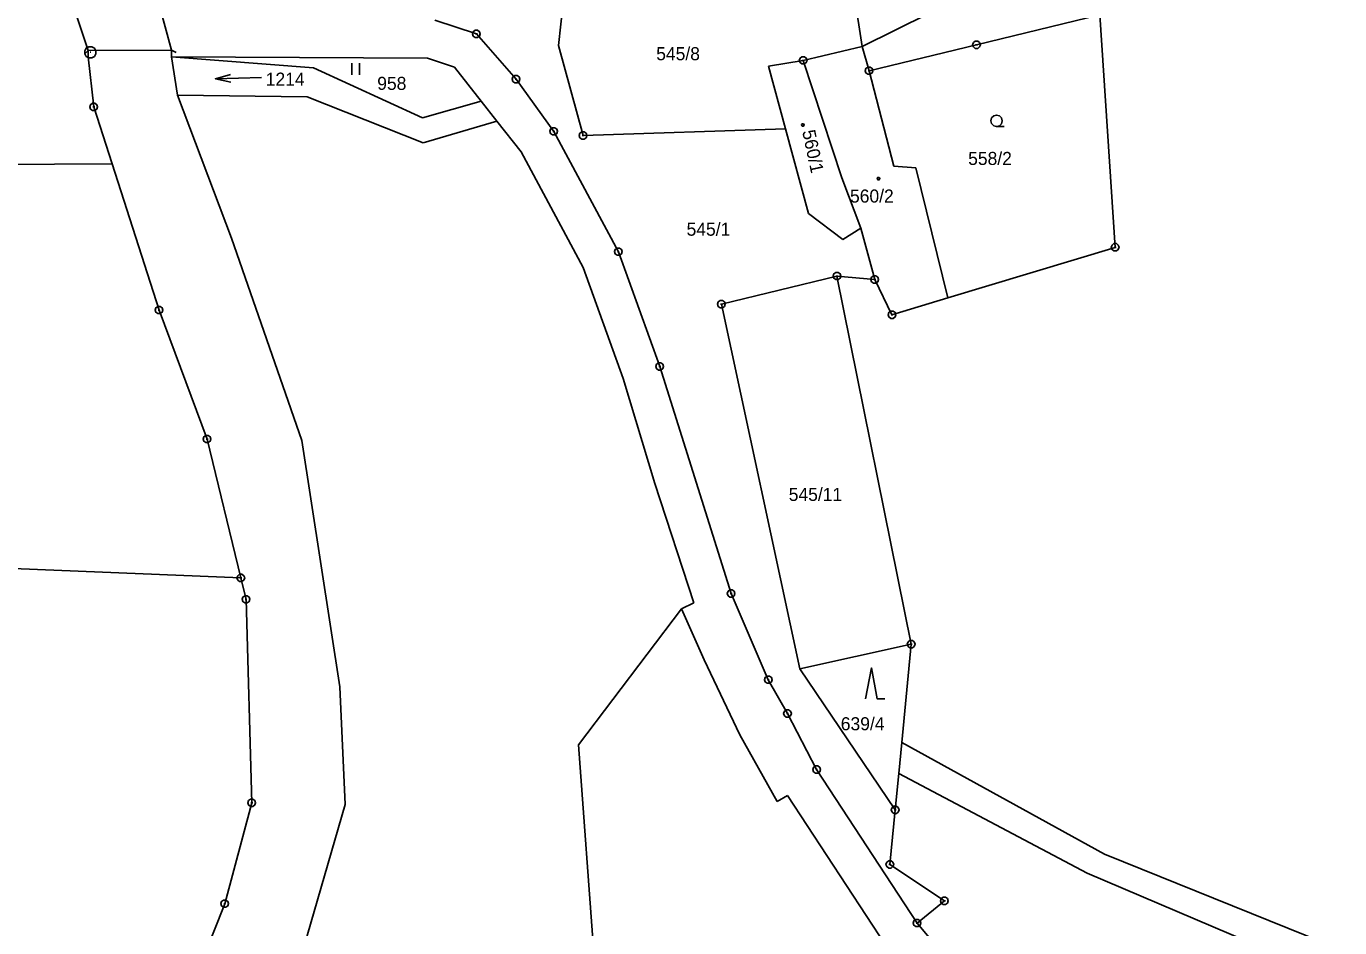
# Model space of a CAD drawing. Extents: x -812394 to -807601, y -1013098 to -1009266.
# Drawn here: x -809003.5 to -808832.6, y -1011807.7 to -1011690.5 of the extents above; entities that cross this region are included whole.
import ezdxf

# ---------------------------------------------------------------- set-up
doc = ezdxf.new("R2010")
doc.units = 0
for name, color, linetype in [('KN_HRANICE', 7, 'Continuous'), ('KN_KULTURY', 7, 'Continuous'), ('KN_MEZNIKY', 7, 'Continuous'), ('KN_PARCELY', 7, 'Continuous'), ('KN_SLUCKY', 7, 'Continuous')]:
    doc.layers.add(name, color=color, linetype=linetype)

# ---------------------------------------------------------------- blocks, each defined once
blk = doc.blocks.new('101')
blk.add_line((-0.05, 0), (0.05, 0))
blk.add_lwpolyline([(0.19, 0.72), (0.53, 0.53), (0.72, 0.19), (0.72, -0.2), (0.53, -0.54), (0.19, -0.73), (-0.2, -0.73), (-0.54, -0.54), (-0.73, -0.2), (-0.73, 0.19), (-0.54, 0.53), (-0.2, 0.72), (0.19, 0.72)])
blk = doc.blocks.new('304')
blk.add_lwpolyline([(0, 0), (-0.38, 0.1), (-0.65, 0.37), (-0.75, 0.74), (-0.65, 1.11), (-0.38, 1.38), (-0.01, 1.48), (0.36, 1.38), (0.63, 1.11), (0.73, 0.73), (0.63, 0.35), (0.36, 0.08), (-0.02, -0.02), (0.98, -0.02)])
blk = doc.blocks.new('306')
for p, q in [((-0.5, 1.5), (-0.5, 0)), ((0.5, 0), (0.5, 1.5))]:
    blk.add_line(p, q)
blk = doc.blocks.new('308')
blk.add_lwpolyline([(-0.75, 0), (0, 4), (0.75, 0), (1.75, 0)])
blk = doc.blocks.new('NAHRADNI_SYMBOL')
blk.add_lwpolyline([(0.09, 0.15), (0.18, 0), (0.09, -0.15), (-0.09, -0.15), (-0.18, 0), (-0.09, 0.15), (0.09, 0.15)])
blk = doc.blocks.new('802')
blk.add_line((-3, 0), (3, 0))
blk.add_lwpolyline([(1, 0.5), (3, 0), (1, -0.5)])
blk = doc.blocks.new('105')
blk.add_line((-0.12, 0), (0.12, 0))
blk.add_lwpolyline([(0.15, 0.48), (0.4, 0.3), (0.5, 0.01), (0.4, -0.28), (0.15, -0.46), (-0.16, -0.46), (-0.41, -0.28), (-0.51, 0.01), (-0.41, 0.3), (-0.16, 0.48), (0.15, 0.48)])
blk = doc.blocks.new('4201')
blk.add_line((0, 0), (-0.5, -0.5))

msp = doc.modelspace()

# ---------------------------------------------------------------- linework, layer by layer
at = {"layer": 'KN_HRANICE'}
for p, q in [((-808896.85, -1011679.68), (-808894.75, -1011693.18)), ((-808894.75, -1011693.18), (-808871.71, -1011681.7)), ((-808995.44, -1011693.68), (-808997.44, -1011687.71)), ((-808984.63, -1011693.65), (-808986.26, -1011687.57)), ((-808933.67, -1011687.5), (-808934.28, -1011693.03)), ((-808879.89, -1011692.95), (-808863.84, -1011689.06)), ((-808861.85, -1011719.28), (-808863.84, -1011689.06)), ((-808950.35, -1011689.74), (-808944.94, -1011691.54)), ((-808944.94, -1011691.54), (-808939.79, -1011697.43)), ((-808995.44, -1011694.53), (-808995.44, -1011693.68)), ((-808984.63, -1011694.5), (-808984.63, -1011693.65)), ((-808934.28, -1011693.03), (-808931.07, -1011704.75)), ((-808902.44, -1011694.98), (-808894.75, -1011693.18)), ((-808894.75, -1011693.18), (-808893.86, -1011696.32)), ((-808893.86, -1011696.32), (-808879.89, -1011692.95)), ((-808994.72, -1011701.03), (-808995.44, -1011694.53)), ((-808984.63, -1011694.5), (-808951.31, -1011694.69)), ((-808966.16, -1011695.95), (-808984.63, -1011694.5)), ((-808983.84, -1011699.49), (-808984.63, -1011694.5)), ((-808951.96, -1011702.46), (-808966.16, -1011695.95)), ((-808951.31, -1011694.69), (-808947.81, -1011695.86)), ((-808947.81, -1011695.86), (-808944.33, -1011700.27)), ((-808902.44, -1011694.98), (-808906.94, -1011695.74)), ((-808904.75, -1011703.86), (-808906.94, -1011695.74)), ((-808897.41, -1011710.26), (-808902.44, -1011694.98)), ((-808939.79, -1011697.43), (-808934.88, -1011704.2)), ((-808893.86, -1011696.32), (-808890.65, -1011708.71)), ((-808994.72, -1011701.03), (-808992.34, -1011708.44)), ((-808944.33, -1011700.27), (-808951.96, -1011702.46)), ((-808944.33, -1011700.27), (-808942.28, -1011702.87)), ((-808951.87, -1011705.7), (-808942.28, -1011702.87)), ((-808942.28, -1011702.87), (-808939.13, -1011706.86)), ((-808934.88, -1011704.2), (-808926.48, -1011719.85)), ((-808931.07, -1011704.75), (-808904.75, -1011703.86)), ((-808904.75, -1011703.86), (-808901.77, -1011714.86)), ((-808939.13, -1011706.86), (-808931.06, -1011721.89)), ((-809019.35, -1011708.55), (-808992.34, -1011708.44)), ((-808992.34, -1011708.44), (-808986.23, -1011727.44)), ((-808890.65, -1011708.71), (-808887.77, -1011708.95)), ((-808887.77, -1011708.95), (-808883.64, -1011725.86)), ((-808894.93, -1011716.8), (-808897.41, -1011710.26)), ((-808901.77, -1011714.86), (-808897.28, -1011718.24)), ((-808897.28, -1011718.24), (-808894.93, -1011716.8)), ((-808893.13, -1011723.47), (-808894.93, -1011716.8)), ((-808926.48, -1011719.85), (-808921.09, -1011734.77)), ((-808861.85, -1011719.28), (-808883.64, -1011725.86)), ((-808931.06, -1011721.89), (-808925.84, -1011736.34)), ((-808913.07, -1011726.68), (-808898.05, -1011723.01)), ((-808888.39, -1011770.88), (-808898.05, -1011723.01)), ((-808898.05, -1011723.01), (-808893.13, -1011723.47)), ((-808893.13, -1011723.47), (-808890.89, -1011728.05)), ((-808902.86, -1011774.06), (-808913.07, -1011726.68)), ((-808883.64, -1011725.86), (-808890.89, -1011728.05)), ((-808979.98, -1011744.21), (-808986.23, -1011727.44)), ((-808921.09, -1011734.77), (-808911.81, -1011764.29)), ((-808925.84, -1011736.34), (-808921.75, -1011749.99)), ((-808975.59, -1011762.27), (-808979.98, -1011744.21)), ((-808921.75, -1011749.99), (-808916.67, -1011765.52)), ((-809026.09, -1011760.16), (-808975.59, -1011762.27)), ((-808974.91, -1011765.05), (-808975.59, -1011762.27)), ((-808911.81, -1011764.29), (-808906.98, -1011775.5)), ((-808974.17, -1011791.5), (-808974.91, -1011765.05)), ((-808916.67, -1011765.52), (-808918.26, -1011766.3)), ((-808918.26, -1011766.3), (-808931.65, -1011783.96)), ((-808918.26, -1011766.3), (-808915.32, -1011772.9)), ((-808902.86, -1011774.06), (-808888.39, -1011770.88)), ((-808889.62, -1011783.66), (-808888.39, -1011770.88)), ((-808915.32, -1011772.9), (-808910.67, -1011782.65)), ((-808890.47, -1011792.42), (-808902.86, -1011774.06)), ((-808906.98, -1011775.5), (-808904.48, -1011779.89)), ((-808904.48, -1011779.89), (-808900.69, -1011787.19)), ((-808910.67, -1011782.65), (-808905.83, -1011791.31)), ((-808931.65, -1011783.96), (-808923.83, -1011891.74)), ((-808890.01, -1011787.67), (-808889.62, -1011783.66)), ((-808889.62, -1011783.66), (-808863.23, -1011798.16)), ((-808900.69, -1011787.19), (-808887.62, -1011807.14)), ((-808890.47, -1011792.42), (-808890.01, -1011787.67)), ((-808865.49, -1011800.66), (-808890.01, -1011787.67)), ((-808977.69, -1011804.62), (-808974.17, -1011791.5)), ((-808905.83, -1011791.31), (-808904.46, -1011790.57)), ((-808904.46, -1011790.57), (-808891.7, -1011810.04)), ((-808891.16, -1011799.52), (-808890.47, -1011792.42)), ((-808863.23, -1011798.16), (-808822.56, -1011814.57)), ((-808884.06, -1011804.26), (-808891.16, -1011799.52)), ((-808824.78, -1011817.93), (-808865.49, -1011800.66)), ((-808986.12, -1011825.88), (-808977.69, -1011804.62)), ((-808887.62, -1011807.14), (-808884.06, -1011804.26)), ((-808878.74, -1011817.7), (-808887.62, -1011807.14))]:
    msp.add_line(p, q, dxfattribs=at)
for points in [[(-808951.87, -1011705.7), (-808966.96, -1011699.71), (-808983.84, -1011699.49)], [(-808959.35, -1011971.59), (-808962.28, -1011929.28), (-808966.55, -1011904.05), (-808970.77, -1011886.31), (-808975.49, -1011831.97), (-808967.41, -1011810.26), (-808962, -1011791.72), (-808962.72, -1011776.44), (-808967.65, -1011744.41), (-808976.79, -1011718.1), (-808983.84, -1011699.49)]]:
    msp.add_lwpolyline(points, dxfattribs=at)
at = {"layer": 'KN_SLUCKY'}
msp.add_line((-808995.44, -1011693.68), (-808984.63, -1011693.65), dxfattribs=at)

# ---------------------------------------------------------------- block references
at = {"layer": 'KN_KULTURY'}
for name, p in [('306', (-808960.66, -1011696.83)), ('304', (-808877.28, -1011703.56)), ('NAHRADNI_SYMBOL', (-808902.48, -1011703.36)), ('NAHRADNI_SYMBOL', (-808892.64, -1011710.33)), ('308', (-808893.57, -1011777.97))]:
    msp.add_blockref(name, p, dxfattribs=at)
at = {"layer": 'KN_KULTURY', "rotation": -178.25778700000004}
msp.add_blockref('802', (-808975.9, -1011697.27), dxfattribs=at)
at = {"layer": 'KN_MEZNIKY'}
for name, p in [('105', (-808944.94, -1011691.54)), ('105', (-808879.89, -1011692.95)), ('101', (-808995.16, -1011693.91)), ('105', (-808902.44, -1011694.98)), ('105', (-808893.86, -1011696.32)), ('105', (-808939.79, -1011697.43)), ('105', (-808994.72, -1011701.03)), ('105', (-808934.88, -1011704.2)), ('105', (-808931.07, -1011704.75)), ('105', (-808926.48, -1011719.85)), ('105', (-808861.85, -1011719.28)), ('105', (-808898.05, -1011723.01)), ('105', (-808893.13, -1011723.47)), ('105', (-808913.07, -1011726.68)), ('105', (-808986.23, -1011727.44)), ('105', (-808890.89, -1011728.05)), ('105', (-808921.09, -1011734.77)), ('105', (-808979.98, -1011744.21)), ('105', (-808975.59, -1011762.27)), ('105', (-808911.81, -1011764.29)), ('105', (-808974.91, -1011765.05)), ('105', (-808888.39, -1011770.88)), ('105', (-808906.98, -1011775.5)), ('105', (-808904.48, -1011779.89)), ('105', (-808900.69, -1011787.19)), ('105', (-808974.17, -1011791.5)), ('105', (-808890.47, -1011792.42)), ('105', (-808891.16, -1011799.52)), ('105', (-808977.69, -1011804.62)), ('105', (-808884.06, -1011804.26)), ('105', (-808887.62, -1011807.14))]:
    msp.add_blockref(name, p, dxfattribs=at)
at = {"layer": 'KN_SLUCKY'}
msp.add_blockref('4201', (-808995.44, -1011693.68), dxfattribs=at)
at = {"layer": 'KN_SLUCKY', "rotation": 108.91927700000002}
msp.add_blockref('4201', (-808984.63, -1011693.65), dxfattribs=at)

# ---------------------------------------------------------------- texts
at = {"layer": 'KN_PARCELY'}
for s, p in [('545/8', (-808921.56, -1011694.95)), ('1214', (-808972.35, -1011698.26)), ('958', (-808957.85, -1011698.81)), ('558/2', (-808880.98, -1011708.57)), ('560/2', (-808896.35, -1011713.46)), ('545/1', (-808917.61, -1011717.77)), ('545/11', (-808904.32, -1011752.25)), ('639/4', (-808897.55, -1011782.07))]:
    msp.add_text(s, height=1.7, dxfattribs=at).set_placement(p)
msp.add_text('560/1', height=1.7, rotation=282.067, dxfattribs=at).set_placement((-808902.58, -1011704.19))

doc.saveas('drawing.dxf')
